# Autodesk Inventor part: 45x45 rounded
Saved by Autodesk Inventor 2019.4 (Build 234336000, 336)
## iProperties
Created: 2020-04
Part Number: 45x45 rounded
Material: Generic
Document SubType Name: Modeling
Designer: Administrator
Density: 1 g/cm^3
Appearance: Default
Title: 45x45 rounded v13
Author: Administrator
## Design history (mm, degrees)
feature "Body1"
body "Solid1"
